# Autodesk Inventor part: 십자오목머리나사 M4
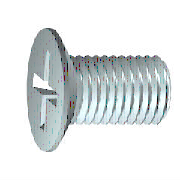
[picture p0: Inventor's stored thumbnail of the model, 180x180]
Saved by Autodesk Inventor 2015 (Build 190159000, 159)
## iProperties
IsCustomPart: 0
Created: 2012-02
Part Number: 십자오목머리나사 M4
Material: 강철, 연강
Description: 십자 오목 머리 나사
Document SubType Name: Modeling
Standard: KS B 1023
Designer: mduedu
Standards Organization: KS
Language: ko-KR
Size Designation: A  M 4 x 12 - H
Categories: <MemberInstance><Categories><Category DisplayName="조임쇠" InternalName="e4da775c-781d-43d5-af7c-5136215cf5a6" Mnemonic="FSTN"><Category DisplayName="볼트" InternalN
Density: 7.86 g/cm^3
Mass: 1.50482 g
Surface Area: 2.78557 cm^2
Volume: 0.191453 cm^3
Appearance: 보라색
Author: mduedu
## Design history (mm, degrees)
body "Solid1"
sketch "스케치1"
  geometry: L1 (2.6, 0)-(12, 0); L2 (12, 0)-(12, 2); L3 (12, 2)-(4.1, 2); L4 (4.1, 2)-(3.671, 1.785); L5 (3.671, 1.785)-(2.7, 1.785); L6 (0, 4.2)-(0, 2.4); L7 (0, 2.4)-(1.801, 1.502); L8 (1.801, 1.502)-(2.6, 0); L9 (-2.4, 0)-(14.4, 0) reference; L10 (0, -0.84)-(0, 5.04) reference; L11 (0, 4.2)-(0.285, 4.2); L12 (0.285, 4.2)-(2.7, 1.785); L13 (4.1, 2)-(2.485, 2)
  constraints: 22 end point, 3 parallel, 3 perpendicular, 2 collinear, 1 horizontal, 1 point on line
  dimensions: "d1" = 7.9 distance of L2.end L3.end (= GEL); "d2" = 4 diameter of L3 L1 (= GD); "d3" = 3.57058 diameter of L5 L1 (= BDM); "d4" = 4.8 diameter of L6.end L1 (= SDM); "d5" = 26.5 deg angle of L7 L1; "d6" = 62 deg angle of L8 L1; "d7" = 2.6 distance from line of L1.start L6 (= INTI); "d8" = 0.42941 horizontal distance of L4.end L3.end (= GAL); "d12" = 8.4 diameter of L11 L1 (= KOD); "d13" = 45 deg angle of L12 L1 (= 0.5 x SEWI); "d15" = 12 distance between parallel lines of L2 L6 (= NLG); "d24" = 2.7 distance from line of L5.end L6 (= KOH)
revolve "본체" stored, may be unused: angle "d16" = 90 deg
sketch "스케치2"
  geometry: L1 (0, 2.4)-(0, 0); L2 (0, 0)-(2.4, 0); L3 (0, 0)-(1.697, 1.697); L4 (0.312, 2.38)-(0.408, 0.734); L5 (2.38, 0.312)-(0.734, 0.408); L6 (0, -5.88)-(0, 5.88) reference; L7 (-5.88, 0)-(5.88, 0) reference; L8 (2.38, -0.312)-(0.734, -0.408); L9 (0.312, -2.38)-(0.408, -0.734); L10 (-0.312, -2.38)-(-0.408, -0.734); L11 (-2.38, -0.312)-(-0.734, -0.408); L12 (-2.38, 0.312)-(-0.734, 0.408); L13 (-0.312, 2.38)-(-0.408, 0.734); A1 r 0.72 centre (0, 0) between (0.72, 0) and (0, 0.72); A2 r 0.84 centre (0, 0) between (0.84, 0) and (0, 0.84); A3 r 2.4 centre (0, 0) between (2.38, 0.312) and (0.312, 2.38); A4 r 2.4 centre (0, 0) between (0.312, 2.38) and (0, 2.4); A5 r 2.4 centre (0, 0) between (2.4, 0) and (2.38, 0.312); A6 r 2.4 centre (0, 0) between (0, -2.4) and (0.312, -2.38); A7 r 2.4 centre (0, 0) between (0.312, -2.38) and (2.38, -0.312); A8 r 2.4 centre (0, 0) between (2.38, -0.312) and (2.4, 0); A9 r 2.4 centre (0, 0) between (0, 2.4) and (-0.312, 2.38); A10 r 2.4 centre (0, 0) between (-0.312, 2.38) and (-2.38, 0.312); A11 r 2.4 centre (0, 0) between (-2.38, 0.312) and (-2.4, 0); A12 r 2.4 centre (0, 0) between (-2.4, 0) and (-2.38, -0.312); A13 r 2.4 centre (0, 0) between (-2.38, -0.312) and (-0.312, -2.38); A14 r 2.4 centre (0, 0) between (-0.312, -2.38) and (0, -2.4); A15 r 0.347 centre (0.755, 0.755) between (0.408, 0.734) and (0.734, 0.408); A16 r 0.347 centre (0.755, -0.755) between (0.734, -0.408) and (0.408, -0.734); A17 r 0.347 centre (-0.755, -0.755) between (-0.408, -0.734) and (-0.734, -0.408); A18 r 0.347 centre (-0.755, 0.755) between (-0.734, 0.408) and (-0.408, 0.734); 3 further points
  constraints: 41 point on circle, 22 end point, 22 symmetric about line, 18 centre point, 11 coincident, 4 point on line, 3 tangent, 2 collinear, 1 perpendicular, 1 vertical, 19 other
  dimensions: "d17" = 1.44 diameter of A1 (= 0.3 x SDM); "d18" = 1.68 diameter of A2 (= 0.35 x SDM); "d19" = 4.8 diameter of A3 (= SDM); "d20" = 45 deg angle of L3 L2; "d21" = 0.3115 distance from line of L4.start L1 (= 0.5 x SBR)
extrude "슬롯" join sketch "스케치2" taper "d22" = 5 deg; stored distance "d79" = 25.4
fillet "모깎기1" dims "d23" = 0.1246 (= 0.2 x SBR)
feature "스레드" dims "d10" = 7.9 (= GEL), "d11" = 0
chamfer "모따기1" distance "d25" = 0.42941 (= -0.5 x SPD + 0.5 x GD); stored, may be unused: second distance "d26" = 0.21471 (= 0.5 x GAL), angle "d88" = 45 deg
workplane "Work Plane2"
other parameters: "NLG" = 12 [user parameter; used in 1 equation term], "GEL" = 7.9 [user parameter; used in 2 equation terms], "GAL" = 0.42941 (= 0.61345 x PTC) [user parameter; used in 3 equation terms], "SPD" = 3.14117 (= NND - 1.2269 x PTC) [user parameter; used in 1 equation term], "KOD" = 8.4 [user parameter; used in 1 equation term], "KOH" = 2.7 [user parameter; used in 1 equation term], "SBR" = 0.623 [user parameter; used in 2 equation terms], "INTI" = 2.6 [user parameter; used in 1 equation term], "SDM" = 4.8 [user parameter; used in 5 equation terms], "GD" = 4 (= NND) [user parameter; used in 2 equation terms], "BDM" = 3.57058 (= NND - GAL) [user parameter; used in 1 equation term], "SEWI" = 90 deg [user parameter; used in 1 equation term], "d9" = 4.8 (= SDM), "d27" = 0, "d91" = 0, "d92" = 0, "GUL" = 0.42941 (= 0.61345 x PTC) [user parameter], "TOA" = 30 deg [user parameter], "EPV" = 4.7 [user parameter], "THREADDIA" = 4 [user parameter; used in 1 equation term], "TPU" = 14.28571 (computed from PTC) [user parameter], "PTC" = 0.7 [user parameter; used in 5 equation terms], "NND" = 4 [user parameter; used in 3 equation terms], "GD1" = 3.14117 (= THREADDIA - 1.2269 x PTC) [user parameter]
